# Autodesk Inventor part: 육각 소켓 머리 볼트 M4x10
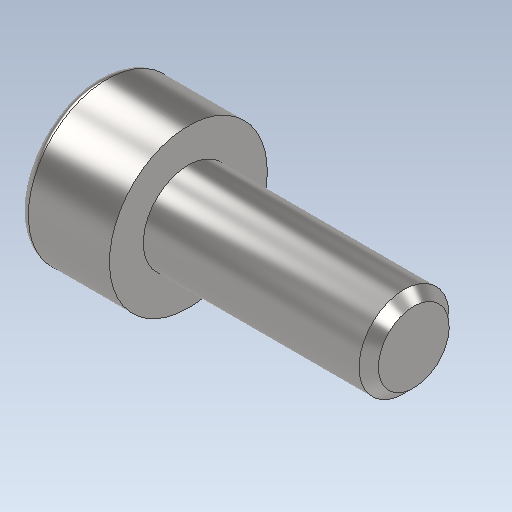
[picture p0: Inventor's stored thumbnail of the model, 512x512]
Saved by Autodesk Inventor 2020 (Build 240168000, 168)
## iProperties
Created: 2024-07
Part Number: 육각 소켓 머리 볼트 M4x10
Material: 강철, 연강
Description: 6각머리 태핑 나사
Document SubType Name: Modeling
Designer: oem
Density: 7.85 g/cm^3
Appearance: 기본값
Author: jhkim
Sending System: Autodesk Inventor 2025
Preprocessor: ST-DEVELOPER v20
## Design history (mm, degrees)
feature "Solid1"
node "솔리드1"
